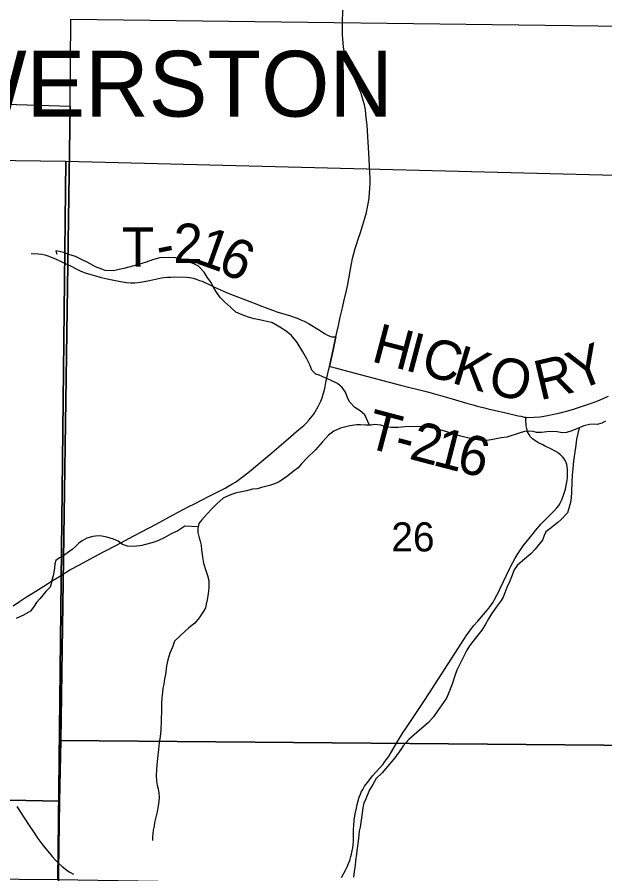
# Model space of a CAD drawing. Extents: x -19.9 to 41.9, y 0 to 32.3.
# Drawn here: x 4.94 to 5.786, y 15.736 to 16.969 of the extents above; entities that cross this region are included whole.
import ezdxf

# ---------------------------------------------------------------- set-up
doc = ezdxf.new("R2010")
doc.units = 0
for name, color, linetype in [('GM_X_Corporation', 7, 'Continuous'), ('GM_X_Corporation_Text', 7, 'Continuous'), ('GM_X_County_Road', 7, 'Continuous'), ('GM_X_Minor_River', 7, 'Continuous'), ('GM_X_Section', 7, 'Continuous'), ('GM_X_Section_Text', 7, 'Continuous'), ('GM_X_Township_Road', 7, 'Continuous'), ('GM_X_Township_Road_Text', 7, 'Continuous')]:
    doc.layers.add(name, color=color, linetype=linetype)

msp = doc.modelspace()

# ---------------------------------------------------------------- linework, layer by layer
at = {"layer": 'GM_X_Corporation'}
for points in [[(5.0171, 16.9663), (5.8519, 16.9554), (5.8404, 15.9209), (5.0026, 15.928), (5.0159, 16.8409)], [(5.0159, 16.8409), (5.0026, 15.928), (5.0009, 15.8404), (3.9969, 15.8607), (4.0122, 16.8721)], [(5.8404, 15.9209), (5.8188, 14.9036), (4.9872, 14.9075), (5.0009, 15.8404), (5.0026, 15.928)], [(3.9969, 15.8607), (5.0009, 15.8404), (4.9872, 14.9075), (4.9863, 14.8396), (3.9837, 14.8466)]]:
    msp.add_lwpolyline(points, close=True, dxfattribs=at)
at = {"layer": 'GM_X_County_Road'}
for points in [[(5.4085, 16.964), (5.4085, 16.965), (5.4088, 16.9748), (5.4102, 16.9996), (5.4109, 17.0087), (5.4114, 17.0134), (5.4122, 17.019), (5.4135, 17.0254), (5.4155, 17.0344), (5.4172, 17.0432), (5.4182, 17.0495), (5.4188, 17.0546), (5.4192, 17.0598), (5.4197, 17.0728), (5.4198, 17.0745)], [(5.3987, 16.5088), (5.4002, 16.5153), (5.4024, 16.5251), (5.4051, 16.537), (5.4083, 16.5505), (5.4105, 16.5596), (5.4143, 16.5756), (5.416, 16.5841), (5.4171, 16.5904), (5.4179, 16.5949), (5.4194, 16.6039), (5.4213, 16.614), (5.423, 16.6216), (5.4248, 16.629), (5.4268, 16.636), (5.4285, 16.6416), (5.4315, 16.6507), (5.4343, 16.6591), (5.4377, 16.67), (5.4406, 16.6798), (5.4429, 16.688), (5.4446, 16.6954), (5.4458, 16.7027), (5.4467, 16.7089), (5.4474, 16.716), (5.4478, 16.7224), (5.4481, 16.7302), (5.4482, 16.7369), (5.4478, 16.7459), (5.4463, 16.7733), (5.4443, 16.8055), (5.4437, 16.8137), (5.443, 16.8208), (5.4421, 16.8292), (5.4414, 16.8354), (5.44, 16.8427), (5.4388, 16.8478), (5.4363, 16.8559), (5.4348, 16.8606), (5.4329, 16.8651), (5.4224, 16.8887), (5.418, 16.8991), (5.4154, 16.9057), (5.4127, 16.9145), (5.4108, 16.9203), (5.4098, 16.9265), (5.4091, 16.9316), (5.4087, 16.9377), (5.4084, 16.9437), (5.4085, 16.964)], [(5.3897, 16.4662), (5.3952, 16.4925), (5.3978, 16.5046), (5.3987, 16.5088)], [(4.9339, 16.1215), (4.9431, 16.1278), (4.9533, 16.1346), (4.9628, 16.1406), (4.978, 16.1501), (4.9894, 16.1572), (4.9998, 16.1636), (5.0158, 16.1734), (5.0294, 16.1809), (5.0495, 16.1916), (5.065, 16.1998), (5.0829, 16.2092), (5.0953, 16.2156), (5.108, 16.2223), (5.1188, 16.2282), (5.1398, 16.2394), (5.1646, 16.2526), (5.1861, 16.264), (5.1954, 16.2686), (5.2175, 16.2798), (5.2347, 16.2886), (5.2392, 16.2911), (5.2434, 16.2935), (5.249, 16.2967), (5.2541, 16.2999), (5.26, 16.3039), (5.2656, 16.3081), (5.2745, 16.3151), (5.2923, 16.3299), (5.3065, 16.3418), (5.3169, 16.3507), (5.3307, 16.3626), (5.3423, 16.3725), (5.3504, 16.3794), (5.3525, 16.3814), (5.3564, 16.3851), (5.3603, 16.3895), (5.362, 16.3914), (5.365, 16.3954), (5.368, 16.3992), (5.3692, 16.401), (5.3735, 16.4086), (5.375, 16.4115), (5.3771, 16.4163), (5.379, 16.4213), (5.3806, 16.4262), (5.3823, 16.4327), (5.3833, 16.4373), (5.3846, 16.4431), (5.3874, 16.456), (5.3897, 16.4662)], [(4.9392, 15.8329), (4.9561, 15.807), (4.9633, 15.7964), (4.9697, 15.787), (4.9754, 15.7792), (4.981, 15.772), (4.9863, 15.7655), (4.99, 15.761), (4.9949, 15.7556), (4.9997, 15.7508), (5.0044, 15.7466), (5.0089, 15.7429), (5.0118, 15.7406), (5.0155, 15.7383), (5.0207, 15.7353)]]:
    msp.add_lwpolyline(points, dxfattribs=at)
at = {"layer": 'GM_X_Minor_River'}
for points in [[(5.4472, 16.3818), (5.4405, 16.3966), (5.434, 16.4026), (5.426, 16.4074), (5.4187, 16.4149), (5.4159, 16.4202), (5.4128, 16.4293), (5.4081, 16.4361), (5.4012, 16.4417), (5.3921, 16.4461), (5.3749, 16.4538), (5.37, 16.4553), (5.3642, 16.4609), (5.3611, 16.4685), (5.3572, 16.4772), (5.3514, 16.4874), (5.3432, 16.5006), (5.3351, 16.5107), (5.3274, 16.5171), (5.3183, 16.523), (5.3122, 16.526), (5.3068, 16.5293), (5.3015, 16.5304), (5.2932, 16.5322), (5.2863, 16.534), (5.281, 16.535), (5.2745, 16.5365), (5.2662, 16.5398), (5.2547, 16.5446), (5.2471, 16.5517), (5.2382, 16.5595), (5.2321, 16.5655), (5.2259, 16.5746), (5.2224, 16.5806), (5.2185, 16.5878), (5.2135, 16.5949), (5.2089, 16.6021), (5.2008, 16.6104), (5.1951, 16.6137), (5.1882, 16.6163), (5.1802, 16.6192), (5.1734, 16.6214), (5.1684, 16.6224), (5.159, 16.6231), (5.1453, 16.6225), (5.1348, 16.6197), (5.1257, 16.6165), (5.1133, 16.6125), (5.0933, 16.6072), (5.0778, 16.6039), (5.0665, 16.6042), (5.0615, 16.6064), (5.0524, 16.6097), (5.0459, 16.6137), (5.0394, 16.6167), (5.0344, 16.6193), (5.0287, 16.6219), (5.0238, 16.6245), (5.0143, 16.6274), (5.0082, 16.6299), (5.0006, 16.6317), (4.9956, 16.6328), (4.9968, 16.6279)], [(5.645, 16.3646), (5.6371, 16.3633), (5.6224, 16.3605), (5.6156, 16.3596), (5.608, 16.3595), (5.6004, 16.3609), (5.5886, 16.3634), (5.5788, 16.3659), (5.567, 16.3695), (5.5571, 16.3728), (5.5457, 16.3761), (5.5328, 16.3785), (5.5187, 16.3798), (5.4983, 16.3792), (5.4885, 16.3786), (5.4786, 16.3785), (5.4691, 16.3799), (5.4634, 16.3817), (5.4547, 16.3827), (5.4498, 16.3819), (5.4419, 16.3817), (5.4343, 16.382), (5.429, 16.3823), (5.4188, 16.3806), (5.4056, 16.3774), (5.3958, 16.3731), (5.3883, 16.3672), (5.3794, 16.3576), (5.3697, 16.3464), (5.3577, 16.3348), (5.3488, 16.3255), (5.3443, 16.3201), (5.3394, 16.3163), (5.3278, 16.3073), (5.317, 16.3003), (5.3102, 16.2972), (5.3034, 16.2948), (5.2917, 16.2919), (5.2861, 16.2903), (5.2785, 16.2895), (5.2702, 16.2874), (5.2634, 16.2858), (5.2555, 16.2842), (5.2498, 16.2822), (5.2438, 16.2802), (5.2363, 16.2767), (5.2269, 16.2678), (5.221, 16.2623), (5.2128, 16.2535), (5.2057, 16.2457), (5.2012, 16.2403), (5.1998, 16.2331), (5.1999, 16.2274), (5.2019, 16.2198), (5.2035, 16.2149), (5.2047, 16.2092), (5.2052, 16.2023), (5.206, 16.1955), (5.2073, 16.189), (5.2081, 16.1833), (5.2113, 16.1727), (5.2137, 16.1655), (5.2157, 16.1583), (5.2158, 16.1484), (5.2155, 16.1427), (5.2145, 16.1362), (5.2134, 16.1305), (5.212, 16.124), (5.2109, 16.1187), (5.2076, 16.1129), (5.2017, 16.1045), (5.1957, 16.0968), (5.1871, 16.0898), (5.1819, 16.0851), (5.1748, 16.0789), (5.1666, 16.0708), (5.1633, 16.0624), (5.1596, 16.0536), (5.1567, 16.044), (5.155, 16.0352), (5.1533, 16.023), (5.1518, 16.0165), (5.1508, 16.0089), (5.1498, 16.0032), (5.1491, 15.9971), (5.1481, 15.9891), (5.1478, 15.9811), (5.1475, 15.9738), (5.1476, 15.9674), (5.1473, 15.9613), (5.147, 15.9563), (5.1465, 15.9426), (5.1455, 15.9335), (5.1441, 15.9243), (5.1435, 15.9148), (5.1425, 15.9064), (5.1414, 15.8976), (5.1408, 15.8927), (5.1405, 15.8854), (5.1402, 15.8778), (5.1403, 15.8694)], [(5.7493, 16.378), (5.7454, 16.3615), (5.7444, 16.3531), (5.7427, 16.3402), (5.7413, 16.3299), (5.7403, 16.3192), (5.7393, 16.3097), (5.7387, 16.2998), (5.7382, 16.286), (5.7379, 16.2769), (5.7361, 16.2685), (5.7347, 16.2635), (5.7326, 16.2555), (5.7236, 16.2458), (5.7184, 16.2416), (5.7068, 16.2323), (5.7015, 16.228), (5.6989, 16.223), (5.6964, 16.2161), (5.6912, 16.21), (5.686, 16.2034), (5.6796, 16.1965), (5.6677, 16.1864), (5.6602, 16.1798), (5.6557, 16.1737), (5.6517, 16.1633), (5.6488, 16.1564), (5.6451, 16.148), (5.6422, 16.1403), (5.6397, 16.1342), (5.6367, 16.1292), (5.6311, 16.1219), (5.623, 16.1104), (5.6189, 16.1031), (5.6145, 16.0954), (5.6093, 16.0869), (5.5996, 16.0746), (5.5911, 16.0642), (5.5874, 16.0581), (5.5841, 16.0512), (5.573, 16.0293), (5.5701, 16.0209), (5.5669, 16.0105), (5.5621, 15.9979), (5.5581, 15.9887), (5.5448, 15.9695), (5.5396, 15.9618), (5.5321, 15.9537), (5.5194, 15.9428), (5.5037, 15.9293), (5.4959, 15.9204), (5.4925, 15.915), (5.484, 15.9031), (5.471, 15.8877), (5.4654, 15.8811), (5.4568, 15.8734), (5.452, 15.8646), (5.4472, 15.8569), (5.4421, 15.8439), (5.4391, 15.8377), (5.4377, 15.8309), (5.4364, 15.8198), (5.4346, 15.8099), (5.4336, 15.803), (5.4325, 15.7973), (5.4312, 15.7866), (5.4298, 15.7756), (5.4292, 15.7695), (5.4285, 15.7641), (5.4271, 15.7546), (5.4264, 15.7477), (5.4254, 15.7393), (5.424, 15.7313)], [(5.7874, 16.3877), (5.7818, 16.3845), (5.7754, 16.3829), (5.7693, 16.3832), (5.764, 16.3827), (5.7561, 16.3807), (5.7493, 16.378), (5.7388, 16.3736), (5.7309, 16.3712), (5.7248, 16.3707), (5.7176, 16.3722), (5.7127, 16.3728), (5.7028, 16.3723), (5.6949, 16.3711), (5.6877, 16.3713), (5.6828, 16.3728), (5.6771, 16.3731), (5.6707, 16.3726), (5.6627, 16.3702), (5.645, 16.3646)], [(5.2002, 16.2354), (5.1812, 16.2366), (5.1711, 16.2296), (5.1617, 16.2253), (5.1515, 16.2194), (5.1433, 16.2155), (5.1372, 16.2135), (5.1316, 16.2119), (5.1195, 16.2087), (5.1086, 16.207), (5.0987, 16.2076), (5.0915, 16.2102), (5.0854, 16.2146), (5.0785, 16.2176), (5.069, 16.2205), (5.0618, 16.2219), (5.0565, 16.2226), (5.0485, 16.2213), (5.0402, 16.2189), (5.0335, 16.2154), (5.0286, 16.2119), (5.0237, 16.2072), (5.0189, 16.203), (5.0121, 16.1979), (5.0069, 16.194), (5.0009, 16.1909), (4.9956, 16.187), (4.9942, 16.182), (4.9935, 16.1759), (4.9918, 16.1649), (4.9896, 16.1588), (4.9886, 16.1534), (4.9871, 16.1484), (4.9811, 16.1423), (4.9726, 16.1319), (4.9677, 16.1264), (4.964, 16.1211), (4.9588, 16.1141), (4.9487, 16.1083), (4.9382, 16.1035)], [(5.1403, 15.8694), (5.1412, 15.8634), (5.1428, 15.8581), (5.1436, 15.8527), (5.1441, 15.8459), (5.1438, 15.8406), (5.1428, 15.8337), (5.1414, 15.8253), (5.1396, 15.8177), (5.1378, 15.8096), (5.1371, 15.8047), (5.1357, 15.799), (5.1347, 15.789), (5.1348, 15.7837)]]:
    msp.add_lwpolyline(points, dxfattribs=at)
at = {"layer": 'GM_X_Section'}
for points in [[(4.1751, 16.7729), (5.0099, 16.7619), (4.9984, 15.7274), (4.1607, 15.7345), (4.1739, 16.6474)], [(5.0099, 16.7619), (6.0276, 16.7357), (6.0103, 15.7106), (4.9984, 15.7274)]]:
    msp.add_lwpolyline(points, close=True, dxfattribs=at)
at = {"layer": 'GM_X_Township_Road'}
for points in [[(4.9601, 16.6287), (4.97, 16.6284), (4.9753, 16.6278), (4.9795, 16.6269), (4.9838, 16.6255), (4.9949, 16.6211), (5.0052, 16.6164), (5.0183, 16.61), (5.0248, 16.6069), (5.0314, 16.6036), (5.0379, 16.6012), (5.0459, 16.5987), (5.0527, 16.5968), (5.0608, 16.5945), (5.0692, 16.5925), (5.0886, 16.5883), (5.097, 16.5869), (5.1037, 16.5864), (5.1094, 16.5866), (5.1172, 16.5876), (5.1303, 16.5899), (5.1477, 16.5937), (5.1509, 16.5942), (5.1562, 16.5946), (5.1613, 16.5949), (5.1658, 16.5951), (5.1835, 16.5948), (5.1884, 16.5941), (5.1931, 16.5932), (5.1978, 16.5918), (5.2024, 16.5902), (5.2061, 16.5888), (5.2099, 16.5872), (5.2165, 16.5841), (5.224, 16.5806), (5.2324, 16.5766), (5.2368, 16.5746), (5.2472, 16.5704), (5.2549, 16.5674), (5.2648, 16.5636), (5.2786, 16.5584), (5.2922, 16.5531), (5.2972, 16.5511), (5.3088, 16.5469), (5.314, 16.5451), (5.3335, 16.539), (5.3375, 16.5377), (5.3431, 16.5356), (5.3484, 16.5334), (5.353, 16.5314), (5.3562, 16.5298), (5.3592, 16.5281), (5.3644, 16.525), (5.3703, 16.5214), (5.3752, 16.5183), (5.3798, 16.5154), (5.3834, 16.5131), (5.3869, 16.5111), (5.3901, 16.5098), (5.3931, 16.509), (5.3961, 16.5088), (5.3987, 16.5088)], [(5.3987, 16.5088), (5.3978, 16.5046), (5.3952, 16.4925), (5.3897, 16.4662)], [(5.3897, 16.4662), (5.3926, 16.4655), (5.4245, 16.4569), (5.4522, 16.4497), (5.492, 16.4395), (5.531, 16.4295), (5.5426, 16.4264), (5.5665, 16.4197), (5.589, 16.4131), (5.5966, 16.4109), (5.6026, 16.4092), (5.613, 16.4065), (5.6195, 16.4049), (5.6268, 16.4032), (5.6438, 16.3994), (5.6614, 16.3954), (5.6653, 16.3945), (5.6707, 16.3934), (5.6723, 16.3931), (5.6734, 16.393), (5.6745, 16.3929), (5.6844, 16.3932), (5.6931, 16.3939), (5.7013, 16.3952), (5.715, 16.398), (5.7218, 16.3996), (5.733, 16.4026), (5.7409, 16.4049), (5.7625, 16.4119), (5.7707, 16.4149), (5.7764, 16.417), (5.7841, 16.4202), (5.7917, 16.4234)], [(5.4067, 15.7305), (5.4098, 15.736), (5.4128, 15.7414), (5.4152, 15.7462), (5.4172, 15.7508), (5.4188, 15.755), (5.4206, 15.7607), (5.4215, 15.7642), (5.4225, 15.7689), (5.4232, 15.7732), (5.4237, 15.7779), (5.424, 15.7833), (5.4244, 15.8004), (5.4247, 15.805), (5.4254, 15.8133), (5.4268, 15.8221), (5.4285, 15.8306), (5.4297, 15.8359), (5.431, 15.8411), (5.4326, 15.8461), (5.4342, 15.8507), (5.4355, 15.8536), (5.4375, 15.8574), (5.4401, 15.8619), (5.4442, 15.8675), (5.4476, 15.8718), (5.4517, 15.8769), (5.4617, 15.8878), (5.4668, 15.894), (5.4695, 15.8974), (5.4717, 15.9004), (5.4754, 15.906), (5.4808, 15.9149), (5.4877, 15.9266), (5.4925, 15.9343), (5.4959, 15.9398), (5.4985, 15.9438), (5.5253, 15.9838), (5.5327, 15.9951), (5.5466, 16.0166), (5.5839, 16.0746), (5.5864, 16.0783), (5.5904, 16.0838), (5.5972, 16.093), (5.6031, 16.0998), (5.6085, 16.1061), (5.6144, 16.1128), (5.6193, 16.1184), (5.6206, 16.1202), (5.6254, 16.127), (5.627, 16.1297), (5.6345, 16.1442), (5.6357, 16.1467), (5.6492, 16.176), (5.6507, 16.1789), (5.657, 16.1902), (5.6601, 16.1953), (5.6637, 16.2008), (5.6688, 16.2081), (5.6833, 16.2264), (5.6864, 16.2302), (5.6946, 16.2396), (5.6999, 16.245), (5.7065, 16.2516), (5.7131, 16.2583), (5.7173, 16.2629), (5.7198, 16.2663), (5.7223, 16.2703), (5.7239, 16.2732), (5.7255, 16.2773), (5.7277, 16.2838), (5.7295, 16.2898), (5.7307, 16.2951), (5.7315, 16.2999), (5.7323, 16.3055), (5.7326, 16.3102), (5.7327, 16.3147), (5.7325, 16.3186), (5.732, 16.3217), (5.7313, 16.3251), (5.7305, 16.328), (5.7291, 16.3309), (5.7278, 16.3333), (5.7259, 16.3359), (5.7226, 16.3391), (5.7188, 16.342), (5.7177, 16.3427), (5.7147, 16.3445), (5.7095, 16.3471), (5.6992, 16.352), (5.6969, 16.3532), (5.6898, 16.3569), (5.6854, 16.3595), (5.6821, 16.362), (5.6794, 16.3649), (5.6772, 16.3682), (5.6751, 16.3721), (5.6738, 16.3771), (5.6731, 16.381), (5.6728, 16.3837), (5.6726, 16.3868), (5.6724, 16.3899), (5.6723, 16.3931)]]:
    msp.add_lwpolyline(points, dxfattribs=at)

# ---------------------------------------------------------------- texts
at = {"layer": 'GM_X_Corporation_Text'}
msp.add_text('BOWERSTON', height=0.0947, rotation=0, dxfattribs=at).set_placement((4.6508, 16.8259))
at = {"layer": 'GM_X_Section_Text'}
msp.add_text('26', height=0.04186, rotation=0, dxfattribs=at).set_placement((5.4787, 16.2))
at = {"layer": 'GM_X_Township_Road_Text'}
for s, rotation, p in [('2', 359.2538, (5.1645, 16.6153)), ('T', 0.1421, (5.0907, 16.6098)), ('1', 340.3171, (5.1944, 16.6158)), ('6', 335.4659, (5.2259, 16.6045)), ('-', 11.2075, (5.145, 16.6111)), ('H', 345.2561, (5.4482, 16.474)), ('I', 345.2405, (5.4965, 16.4613)), ('C', 344.7918, (5.519, 16.4554)), ('Y', 21.433, (5.7462, 16.4306)), ('K', 343.3751, (5.5637, 16.4432)), ('O', 347.5106, (5.6159, 16.4278)), ('R', 13.3735, (5.6925, 16.4172)), ('T', 345.1747, (5.4392, 16.3505)), ('2', 345.2642, (5.5027, 16.3337)), ('1', 345.4929, (5.5365, 16.3248)), ('6', 346.0803, (5.5707, 16.3159)), ('-', 345.1994, (5.4803, 16.3396))]:
    msp.add_text(s, height=0.0568, rotation=rotation, dxfattribs=at).set_placement(p)

doc.saveas('drawing.dxf')
